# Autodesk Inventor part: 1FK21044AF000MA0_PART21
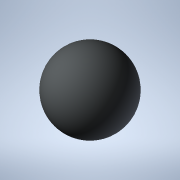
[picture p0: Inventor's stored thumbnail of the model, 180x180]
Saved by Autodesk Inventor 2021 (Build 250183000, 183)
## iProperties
Created: 2025-04
Part Number: 1FK21044AF000MA0_PART21
Material: Generic
Catalog Web Link: www.3dfindit.com
Description: -Servo synchronous motor
Document SubType Name: Modeling
Designer: psAdmin
Mass: 0.137258 g
Surface Area: 1.2868 cm^2
Volume: 0.137258 cm^3
Density: 1 g/cm^3
Appearance: PSOLRGB-212-217-219
Category: PARTsolutions
Title: 1FK21044AF000MA0_PART21
Author: Cadenas PARTsolutions
Comments: Servo synchronous motor
Sending System: PARTsolutions
Preprocessor: ST-DEVELOPER v19.3
PSOL_IDENT_0: {$CADENAS_DATA/23d-libs/siemens_ag/_cat_/39/c4/1fk21044af000ma0.prj},216 {VTYP=3D},{NB=1FK21044AF000
PSOL_IDENT_1: MA0_PART21},{LINA=1FK21044AF000MA0_PART21},{NN=1FK21044AF000MA0_PART21},{NOPRJ=TRUE},{DATE=19.08.202
PSOL_IDENT_2: 5 14:00:33},{GEOMDATE=30.07.2025 02:02:22},{VERSION=},{LINEID=10},{WBVAR=},{WBNUMERIC=}  {NB=1FK2104
PSOL_IDENT_3: 4AF000MA0_PART21},{LINA=1FK21044AF000MA0_PART21},{KT=DUMMY},{PREVIEW=../../../_pool_/cb/72/p_d211_xx
PSOL_IDENT_4: _00434j.png},{DESCSHORT=SIMOTICS S-1FK2 HD, SINAMICS S210 3AC 400V-480V, 1.27 Nm, 3000 rpm},{DESCLON
PSOL_IDENT_5: G=SIMOTICS S-1FK2 HD servo motor M0=1.27 Nm; PN = 0.4 kW at nN=3000 rpm (380-480 V); PN = 0.2 kW at
PSOL_IDENT_6: nN=1500 rpm (200-240 V); degree of protection IP64; cylindrical shaft D19x40mm; absolute encoder 22-
PSOL_IDENT_7: bit + 12-bit multiturn (encoder AM22DQC); with OCC interface; plug size M17, rotatable; SIMOTICS S-1
PSOL_IDENT_8: FK2 servomotorfor a wide range of uses in industrial environments. SIMOTICS S‑1FK2 servomotors are c
PSOL_IDENT_9: ompact synchronous motors with a high dynamic performance that set themselves apart as a result of t
PSOL_IDENT_10: heir high power density, degree of protection and overload capability. The motors are available in t
PSOL_IDENT_11: wo variants: as High Dynamic variant (highest dynamic performance as a result of the low intrinsic m
PSOL_IDENT_12: oment of inertia for applications demanding a high dynamic performance with low moved masses) - and
PSOL_IDENT_13: as Compact variant (precise and stable closed-loop control for medium up to large moved masses as a
PSOL_IDENT_14: result of a medium intrinsic moment of inertia). SIMOTICSS‑1FK2 servomotors fully exploit their stre
PSOL_IDENT_15: ngths in a system with the SINAMICSS210 frequency converter and simple connection using the one cabl
PSOL_IDENT_16: e connection (OCC). Advantages include the short control and positioning times, fast and precise cor
PSOL_IDENT_17: rection of disturbing quantities as well as stable control with a high dynamic performance. The serv
PSOL_IDENT_18: o motors can be configured to address a wide range of requirements. For example with and without hol
PSOL_IDENT_19: ding brake, IP64 or IP65 degree of protection, singleturn or multiturn absolute encoders - to name j
PSOL_IDENT_20: ust a few. Further, the servomotors are available in different shaft heights extending from 20 to 10
PSOL_IDENT_21: 0. A shaft sealing ring is available to achieve an IP65 degree of protection and for subsequent moun
PSOL_IDENT_22: ting at the motor or as spare part. SIMOTICS - the optimum motor for each and every motion control a
PSOL_IDENT_23: pplication.},{INTNO=804766906428},{SUPPLIERALTNO=1FK2104-4AF00-0MA0},{MANUID=1FK21044AF000MA0},{MANU
PSOL_IDENT_24: NAME=Siemens},{MANUTYPEDESC=Synchronous motor 1FK2-HD 1.27 NM},{AAU732=SIMOTICS},{AAO057=S-1FK2},{AA
PSOL_IDENT_25: U734=SIMOTICS S-1FK2 HD servo motor M0=1.27 Nm; PN = 0.4 kW at nN=3000 rpm (380-480 V); PN = 0.2 kW
PSOL_IDENT_26: at nN=1500 rpm (200-240 V); degree of protection IP64; cylindrical shaft D19x40mm; absolute encoder
PSOL_IDENT_27: 22-bit + 12-bit multiturn (encoder AM22DQC); with OCC interface; plug size M17, rotatable;},{AAW338=
PSOL_IDENT_28: Synchronous motor 1FK2-HD 1.27 NM},{AAO742=SIMOTICS},{AAO663=4042948693322},{NOCUPEROU=1},{PRICEQUAN
PSOL_IDENT_29: TITY=1},{QUANTITYMIN=1},{QUANTITYINT=1},{CTN=85015100},{COO=DE},{AAO676=1FK2104-4AF00-0MA0},{AAO677=
PSOL_IDENT_30: Siemens AG},{ORDERUNIT=C62},{CONTENTUNIT=C62}
NB: 1FK21044AF000MA0_PART21
NT: Servo synchronous motor
NBSYN: $MANUID._PART21
LINA: 1FK21044AF000MA0_PART21
CATALOG: SIEMENS
PREVIEW: ../../../_pool_/cb/72/p_d211_xx_00434j.png
DESCSHORT: SIMOTICS S-1FK2 HD, SINAMICS S210 3AC 400V-480V, 1.27 Nm, 3000 rpm
DESCLONG: SIMOTICS S-1FK2 HD servo motor M0=1.27 Nm; PN = 0.4 kW at nN=3000 rpm (380-480 V); PN = 0.2 kW at nN=1500 rpm (200-240 V); degree of protection IP64; cylindrica
INTNO: 804766906428
SUPPLIERALTNO: 1FK2104-4AF00-0MA0
MANUID: 1FK21044AF000MA0
MANUNAME: Siemens
MANUTYPEDESC: Synchronous motor 1FK2-HD 1.27 NM
AAU732: SIMOTICS
AAO057: S-1FK2
AAU734: SIMOTICS S-1FK2 HD servo motor M0=1.27 Nm; PN = 0.4 kW at nN=3000 rpm (380-480 V); PN = 0.2 kW at nN=1500 rpm (200-240 V); degree of protection IP64; cylindrica
AAW338: Synchronous motor 1FK2-HD 1.27 NM
AAO742: SIMOTICS
AAO663: 4042948693322.0
NOCUPEROU: 1
PRICEQUANTITY: 1
QUANTITYMIN: 1
QUANTITYINT: 1
CTN: 85015100
COO: DE
ARTICLENO: 1FK21044AF000MA0_PART21
BOMINFO: 1FK21044AF000MA0_PART21
CREATOR: CADENAS GmbH
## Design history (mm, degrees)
feature "2025_04_17_15_01_28_0038"
body "Solid1"
